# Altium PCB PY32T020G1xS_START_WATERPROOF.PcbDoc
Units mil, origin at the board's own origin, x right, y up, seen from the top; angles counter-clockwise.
Board outline 3313.26 x 4614.31 mil, 2 copper layers (Top Layer, Bottom Layer); 71 components, 60 nets, 191 pads, 58 vias.
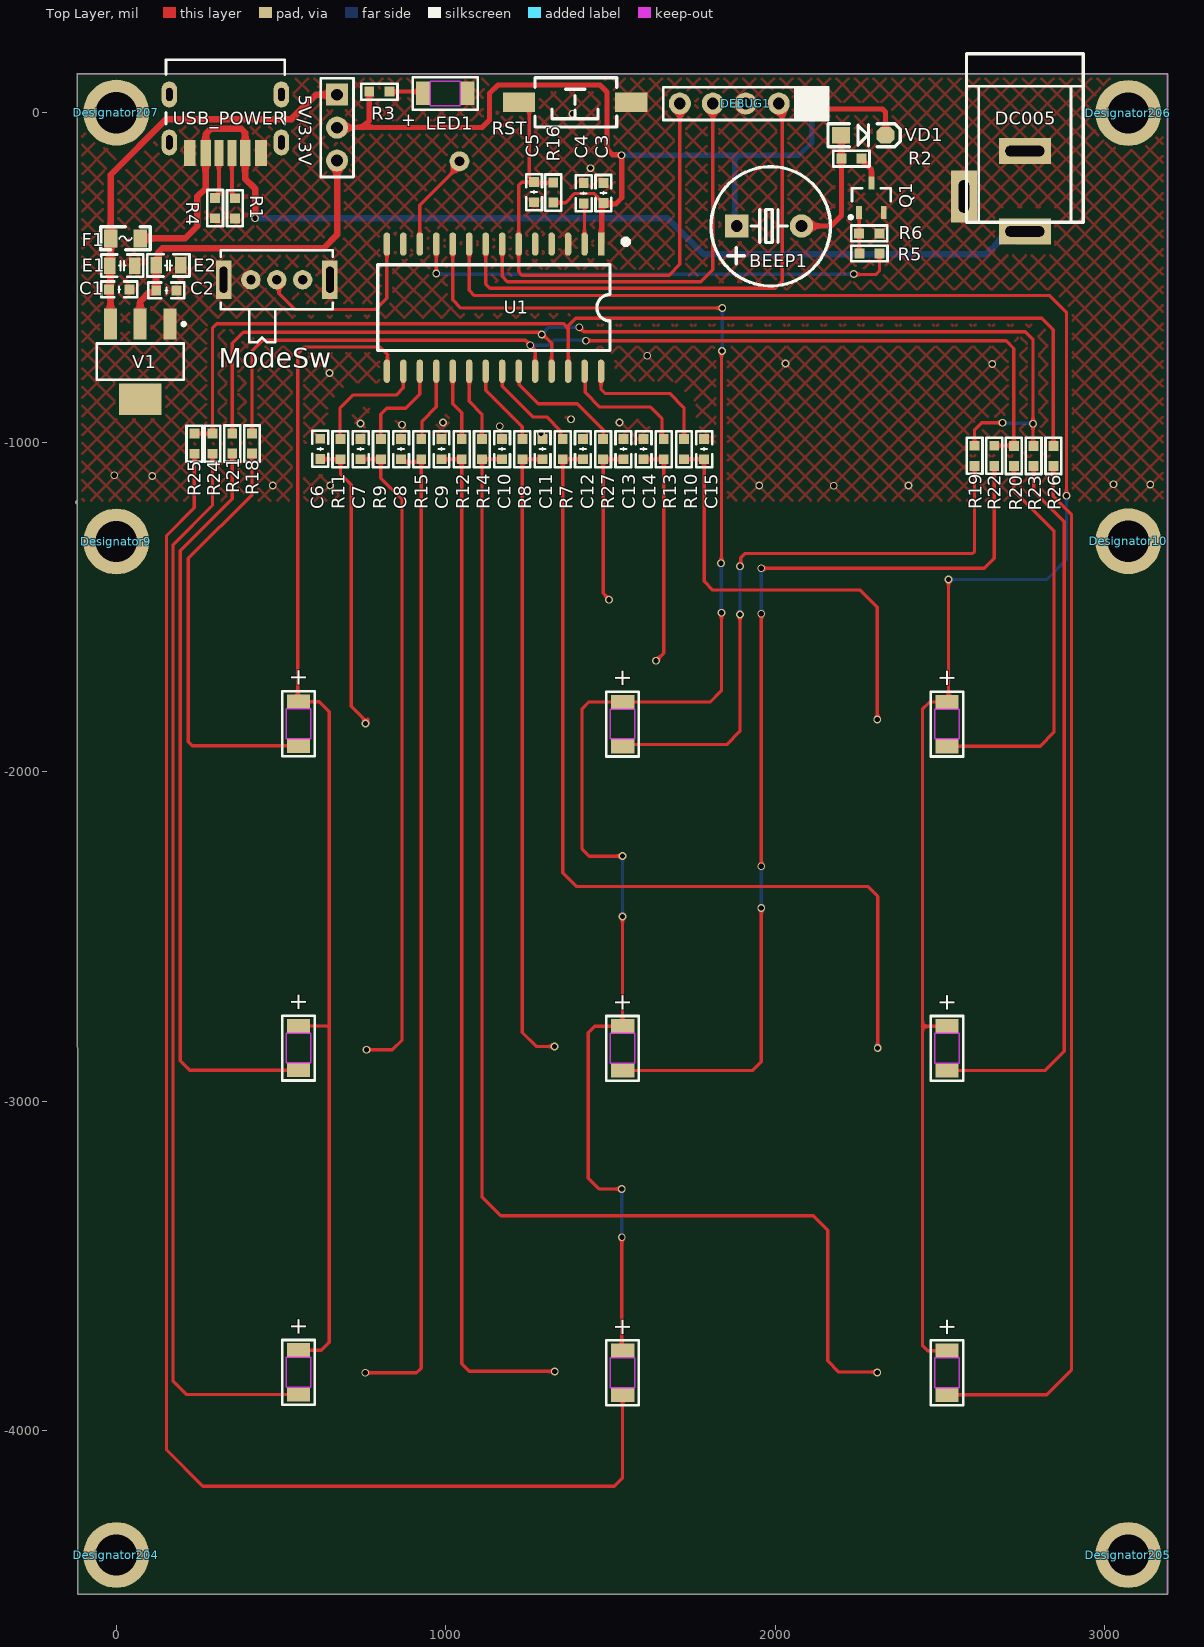
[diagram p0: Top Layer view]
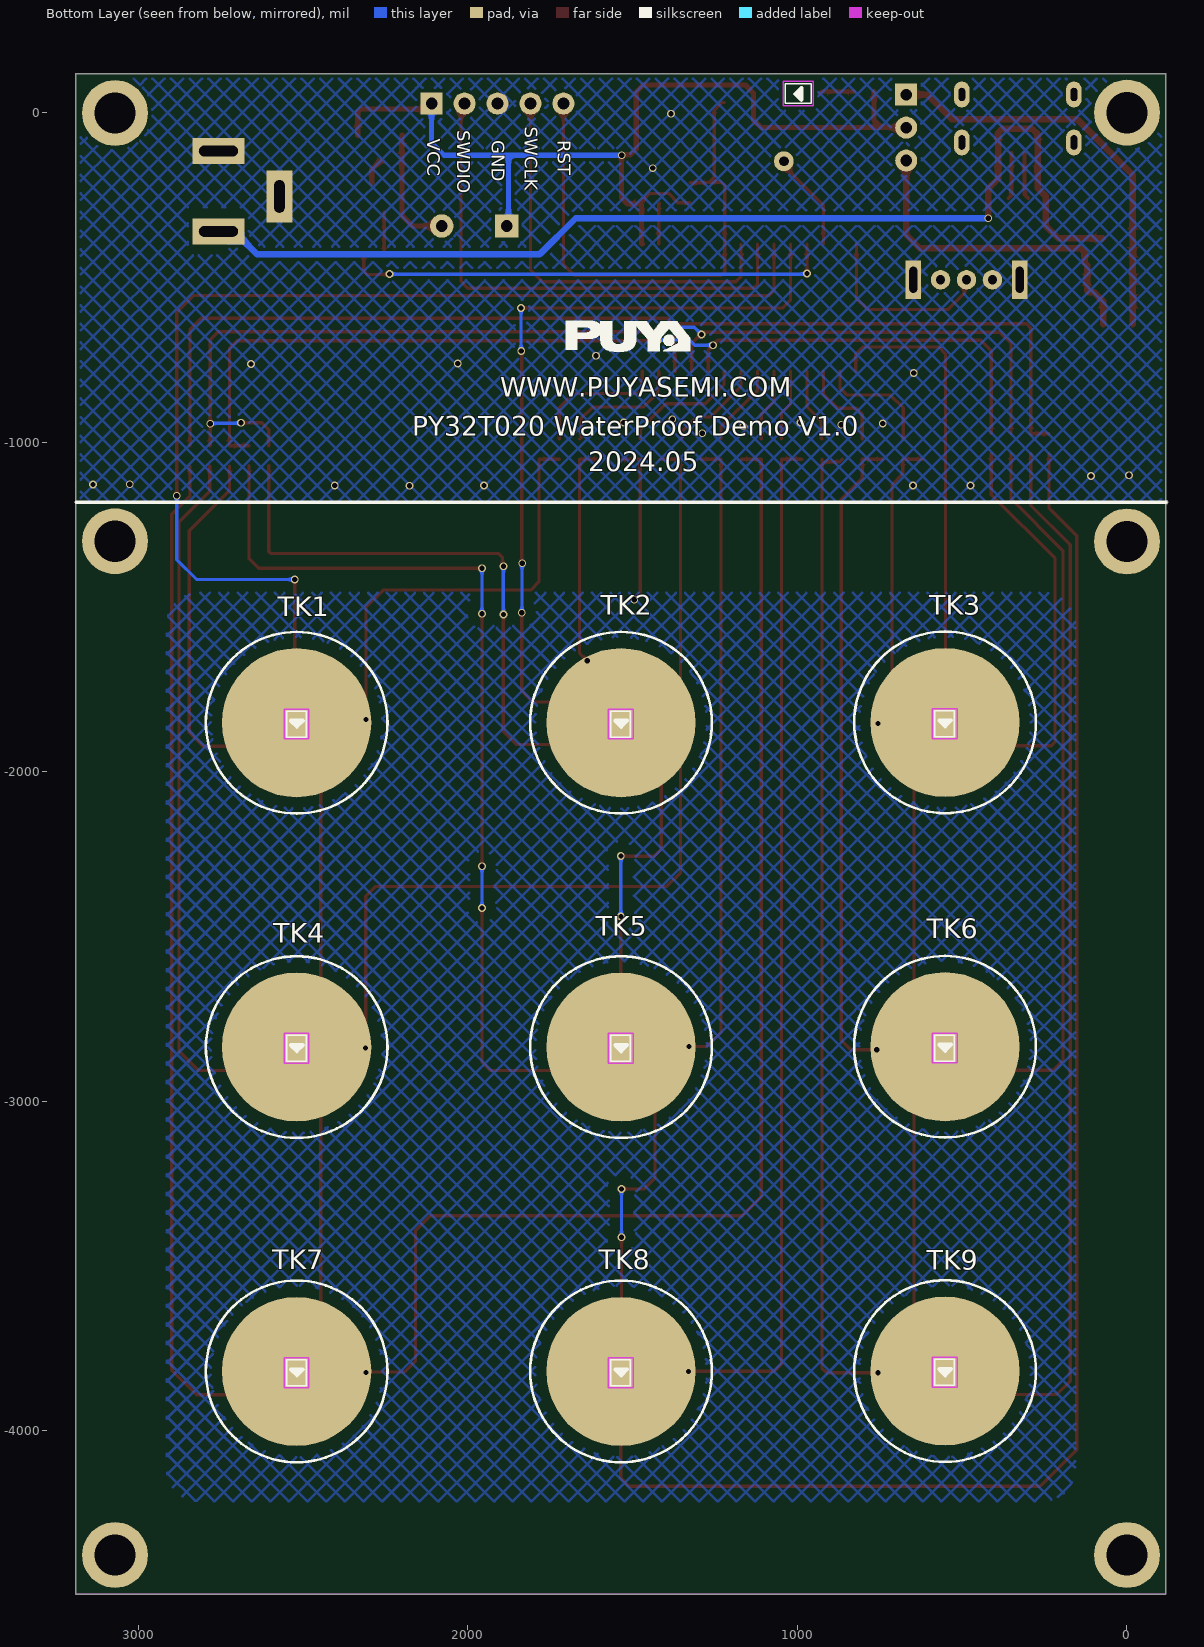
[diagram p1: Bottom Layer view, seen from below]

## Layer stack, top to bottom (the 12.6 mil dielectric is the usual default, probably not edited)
Top Solder: solder mask 0.4, Solder Resist, Dk 3.5
Top Layer: signal copper 1.4
Dielectric 1: dielectric 12.6, FR-4, Dk 4.8
Bottom Layer: signal copper 1.4
Bottom Solder: solder mask 0.4, Solder Resist, Dk 3.5

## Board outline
-117.65,-4495.93 3190.12,-4495.93 3189.95,-4494.9 3189.95,117.87 3189.43,118.38 -117.65,118.38 -118.17,117.87 -118.17,-1187.31 cw(c-118.12,-1182.29)

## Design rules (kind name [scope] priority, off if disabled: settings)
Clearance [InNet('TK1')] p1: gap=30.24 ignorepadtopadclearanceinfootprint=FALSE
Clearance Clearance_21 [InNet('TK2')] p2: gap=30.24 ignorepadtopadclearanceinfootprint=FALSE
Clearance Clearance_20 [InNet('TK3')] p3: gap=30.24 ignorepadtopadclearanceinfootprint=FALSE
Clearance Clearance_19 [InNet('TK4')] p4: gap=30.24 ignorepadtopadclearanceinfootprint=FALSE
Clearance Clearance_18 [InNet('TK5')] p5: gap=30.24 ignorepadtopadclearanceinfootprint=FALSE
Clearance Clearance_17 [InNet('TK6')] p6: gap=30.24 ignorepadtopadclearanceinfootprint=FALSE
Clearance Clearance_16 [InNet('TK7')] p7: gap=30.24 ignorepadtopadclearanceinfootprint=FALSE
Clearance Clearance_15 [InNet('TK8')] p8: gap=30.24 ignorepadtopadclearanceinfootprint=FALSE
Clearance Clearance_14 [InNet('TK9')] p9: gap=30.24 ignorepadtopadclearanceinfootprint=FALSE
Clearance Clearance_13 [InNet('TK_GNG')] p10: gap=30.24 ignorepadtopadclearanceinfootprint=FALSE
Clearance Clearance_12 [InNet('TK_GUARD')] p11: gap=30.24 ignorepadtopadclearanceinfootprint=FALSE
Clearance Clearance_25 [InNet('TK_GUARD_GNG')] p12: gap=30.24 ignorepadtopadclearanceinfootprint=FALSE
Clearance Clearance_23 [InNet('TK_SH_GND')] p13: gap=30.24 ignorepadtopadclearanceinfootprint=FALSE
Clearance Clearance_8 [InNet('NetR7_2')] p14: gap=30.24 ignorepadtopadclearanceinfootprint=FALSE
Clearance Clearance_22 [InNet('NetR8_2')] p15: gap=30.24 ignorepadtopadclearanceinfootprint=FALSE
Clearance Clearance_10 [InNet('TK_GUARD_GNG')] p16: gap=30.24 ignorepadtopadclearanceinfootprint=FALSE
Clearance Clearance_11 [InNet('TK_SH_GND')] p17: gap=30.24 ignorepadtopadclearanceinfootprint=FALSE
Clearance Clearance_7 [InNet('NetR9_2')] p18: gap=30.24 ignorepadtopadclearanceinfootprint=FALSE
Clearance Clearance_9 [InNet('NetR11_2')] p19: gap=30.24 ignorepadtopadclearanceinfootprint=FALSE
Clearance Clearance_6 [InNet('NetR10_2')] p20: gap=30.24 ignorepadtopadclearanceinfootprint=FALSE
Clearance Clearance_5 [InNet('NetR12_2')] p21: gap=30.24 ignorepadtopadclearanceinfootprint=FALSE
Clearance Clearance_4 [InNet('NetR13_2')] p22: gap=30.24 ignorepadtopadclearanceinfootprint=FALSE
Clearance Clearance_3 [InNet('NetR14_2')] p23: gap=30.24 ignorepadtopadclearanceinfootprint=FALSE
Clearance Clearance_2 [InNet('NetR15_2')] p24: gap=30.24 ignorepadtopadclearanceinfootprint=FALSE
Clearance Clearance_1 [All] p25: gap=10 ignorepadtopadclearanceinfootprint=FALSE except(0: Arc-Hole Track-Hole SMDPad-Hole THPad-Hole Via-Hole Fill-Hole Poly-Hole Region-Hole Text-Hole)
PlaneConnect PlaneConnect_1 [InNet('GND')] p1: planeconnectstyle=Direct reliefexpansion=20 reliefentries=4 reliefconductorwidth=10 reliefairgap=10
PlaneConnect [All] p2: planeconnectstyle=Direct reliefexpansion=20 reliefentries=4 reliefconductorwidth=10 reliefairgap=10
PolygonConnect PolygonConnect_1 [InNet('GND')] p1: connectstyle=Direct reliefconductorwidth=10 reliefentries=4 polygonreliefangle="90 Angle" airgapwidth=10
PolygonConnect [All] p2: connectstyle=Direct reliefconductorwidth=10 reliefentries=4 polygonreliefangle="90 Angle" airgapwidth=10
RoutingVias [All] p1: holewidth=28 width=50 viastyle="Through Hole" minholewidth=28 minwidth=50 maxholewidth=28 maxwidth=50
SolderMaskExpansion [All] p1: expansion=4 istentingtop=FALSE
Width [All] p1: maxlimit=23.62 minlimit=10 preferedwidth=10
29 further rules are at their usual default settings.

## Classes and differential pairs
component class PY32T020_StartKit_V1.0: BEEP1 C1 C2 C3 C4 C5 DEBUG1 E1 E2 F1 Q1 R1 R2 R3 R4 R5 R6 R7 R8 R9 R10 R11 R12 R13 R14 R15 R16 R18 R19 R20 R21 R22 R23 R24 R25 R26 RST U1 USB_POWER V1 VD1

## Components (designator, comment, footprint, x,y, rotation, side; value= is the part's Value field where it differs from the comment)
5V/3.3V "Comment" HDR2.54-LI-3P 669.96,-45.29 r270 top
BEEP1 "DC5V" "BEEP 5x9x5.5" 1980.89,-343.89 r270 top
C1 "104" "C 0603_L" 8.96,-536.29 r180 top
C2 "104" "C 0603_L" 151.96,-539.29 r180 top (schematic designator C3)
C3 "104" "C 0603_L" 1478.07,-243.93 r270 top
C4 "22NF" "C 0603_L" 1418.36,-244.52 r270 top
C5 "104" "C 0603_L" 1267.96,-241.29 r90 top
C6 "5PF" "C 0603_L" 619,-1020 r270 top (schematic designator C3)
C7 "5PF" "C 0603_L" 741.63,-1021 r90 top (schematic designator C3)
C8 "5PF" "C 0603_L" 864.26,-1021 r90 top (schematic designator C3)
C9 "5PF" "C 0603_L" 986.89,-1021 r90 top (schematic designator C3)
C10 "5PF" "C 0603_L" 1170.84,-1021 r90 top (schematic designator C3)
C11 "5PF" "C 0603_L" 1293.47,-1021 r90 top (schematic designator C3)
C12 "5PF" "C 0603_L" 1416.1,-1021 r90 top (schematic designator C3)
C13 "5PF" "C 0603_L" 1538.74,-1021 r90 top (schematic designator C3)
C14 "5PF" "C 0603_L" 1600.05,-1021 r90 top (schematic designator C3)
C15 "5PF" "C 0603_L" 1784,-1021 r90 top (schematic designator C3)
DC005 "Comment" DC-005 2756.96,-116.29 r90 top
DEBUG1 "ISP" ISP_DIP_2.54_5P 2110.15,27.72 r180 top
Designator9 "Comment" "M3 125X200"#1 0,-1300.4 r0 top
Designator10 "Comment" "M3 125X200"#2 3070.78,-1260.84 r0 top
Designator204 "Comment" "M3 125X200"#3 917.62,-3625.4 r0 top
Designator205 "Comment" "M3 125X200"#4 1567.95,-3583.28 r0 top
Designator206 "Comment" "M3 125X200"#5 2115.25,-689.08 r0 top
Designator207 "Comment" "M3 125X200"#6 166.83,-122.51 r0 top
E1 "10uF/10V" "C 0805_L" 17.96,-464.29 r0 top
E2 "10uF/10V" "C 0805_L" 158.37,-463.29 r0 top
F1 "500ma" "FU 0805" 27.96,-381.29 r180 top
LED1 "Comment" T-LED#1 993.96,57.71 r180 bottom
ModeSw "Comment" SK-12D07VG3 487,-507 r0 top
Q1 "SS8050" SOT23-3L 2291.65,-257.37 r0 top
R1 "5.1K" "R 0603_L" 360.03,-290.19 r90 top
R2 "200R" "R 0603_L" 2230.96,-139.29 r180 top
R3 "1K" "R 0603_L" 798.37,63.71 r180 top
R4 "5.1K" "R 0603_L" 300.03,-289.6 r90 top
R5 "1K" "R 0603_L" 2285.37,-427.29 r0 top
R6 "10K" "R 0603_L" 2284.81,-366.29 r180 top
R7 "4.3K" "R 0603_L" 1354.79,-1021 r270 top
R8 "4.3K" "R 0603_L" 1232.16,-1021 r270 top
R9 "4.3K" "R 0603_L" 802.95,-1021 r270 top
R10 "4.3K" "R 0603_L" 1722.68,-1021 r270 top
R11 "4.3K" "R 0603_L" 680.32,-1021 r270 top
R12 "4.3K" "R 0603_L" 1048.21,-1021 r270 top
R13 "4.3K" "R 0603_L" 1661.37,-1021 r270 top
R14 "4.3K" "R 0603_L" 1109.53,-1021 r270 top
R15 "4.3K" "R 0603_L" 925.58,-1021 r270 top
R16 "10K" "R 0603_L" 1325.96,-242.29 r270 top
R18 "1K" "R 0603_L" 411.89,-1003.95 r270 top
R19 "1K" "R 0603_L" 2604.32,-1041.12 r270 top
R20 "1K" "R 0603_L" 2723.59,-1041.66 r270 top
R21 "1K" "R 0603_L" 351.89,-1003.95 r270 top
R22 "1K" "R 0603_L" 2664.32,-1041.12 r270 top
R23 "1K" "R 0603_L" 2783.59,-1041.66 r270 top
R24 "1K" "R 0603_L" 291.89,-1004.54 r270 top
R25 "1K" "R 0603_L" 236.89,-1004.54 r270 top
R26 "1K" "R 0603_L" 2843.59,-1041.66 r270 top
R27 "4.3K" "R 0603_L" 1477.42,-1021 r270 top
RST "6x6x5" "TSW SMD-3*6*5" 1392.05,31.19 r180 top
TK1 "Comment" T-LED#2 2519.62,-1851.19 r90 bottom
TK2 "Comment" T-LED#2 1535.36,-1851.19 r90 bottom
TK3 "Comment" T-LED#2 552.18,-1850.08 r90 bottom
TK4 "Comment" T-LED#2 2519.62,-2835.44 r90 bottom
TK5 "Comment" T-LED#2 1535.36,-2835.44 r90 bottom
TK6 "Comment" T-LED#2 552.18,-2834.34 r90 bottom
TK7 "Comment" T-LED#2 2519.62,-3819.69 r90 bottom
TK8 "Comment" T-LED#2 1535.36,-3819.69 r90 bottom
TK9 "Comment" T-LED#2 552.18,-3818.59 r90 bottom
U1 "PY32T020G16" SOP28_L 1146.02,-591.58 r270 top
USB_POWER "USB-C" USB-C/S_C 331.05,155.67 r180 top (schematic designator USB_POWER1)
V1 "AMS1117-3V3" SOT223_N 72.51,-755.46 r270 top
VD1 "A7" SOD-123 2266.96,-68.29 r0 top

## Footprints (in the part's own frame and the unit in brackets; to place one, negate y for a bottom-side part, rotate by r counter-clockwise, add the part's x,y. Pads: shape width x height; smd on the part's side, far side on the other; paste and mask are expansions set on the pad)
"BEEP 5x9x5.5" [mm] "5*9*5.5mm(脚距,直径,高度)"
  rect 1.8x1.8 hole 0.9: 1(0,-2.5)
  round 1.8 hole 0.9: 2(0,2.5)
  silkscreen extent -4.57,-4.47 4.62,4.73, body extent -4.5,-4.5 4.5,4.5, height 5.45
"C 0603_L" [mil] "无极性贴片电容"
  rect 30x30 smd: 1(-30.59,0) 2(30.59,0)
  silkscreen extent -55,-24 55,24, body extent -31,-16 31,16, height 32
"C 0805_L" [mil] "无极性贴片电容"
  rect 35x50 smd: 1(-37.4,0) 2(37.4,0)
  silkscreen extent -64,-34 64,34, body extent -39,-24 39,24, height 20
DC-005 [mm] "5.5*2.1mm，DC30V,2.5A"
  rect 2x4 hole 0.8 slot 3 at 90 deg: 1(-6.2,0) 2(0,0)
  rect 4x2 hole 0.8 slot 2.5 at 0 deg: 3(-3.5,4.7)
  silkscreen extent -5.48,-4.5 7.5,4.5, body extent -6.55,-4.5 7.5,4.8, height 11.2
"FU 0805" [mil] "贴片保险丝"
  rect 40x55 smd: 1(-45,0) 2(45,0)
  silkscreen extent -75,-35 75,35, body extent -39,-24 39,24, height 20
HDR2.54-LI-3P [mm] "排针，3脚"
  rect 1.7x1.7 hole 0.9: 1(-2.54,0)
  round 1.7 hole 0.9: 2(0,0) 3(2.54,0)
  silkscreen extent -3.81,-1.27 3.81,1.27, body extent -3.81,-1.27 3.81,1.27, height 8.5
ISP_DIP_2.54_5P [mm] "5P 下载端口"
  rect 1.7x1.7 hole 0.9: 1(0,0)
  round 1.7 hole 0.9: 2(2.54,0) 3(5.08,0) 4(7.62,0) 5(10.16,0)
  silkscreen extent -1.27,-1.27 11.43,1.27
"M3 125X200"#1 [mil] "M3螺丝孔，孔125Mil，焊盘200Mil"
  round 200 hole 125: 1(0,-1)
"M3 125X200"#2 [mil] "M3螺丝孔，孔125Mil，焊盘200Mil"
  round 200 hole 125: 1(0.07,-39.56)
"M3 125X200"#3 [mil] "M3螺丝孔，孔125Mil，焊盘200Mil"
  round 200 hole 125: 1(-917.62,-751.38)
"M3 125X200"#4 [mil] "M3螺丝孔，孔125Mil，焊盘200Mil"
  round 200 hole 125: 1(1502.83,-793.5)
"M3 125X200"#5 [mil] "M3螺丝孔，孔125Mil，焊盘200Mil"
  round 200 hole 125: 1(955.53,688.08)
"M3 125X200"#6 [mil] "M3螺丝孔，孔125Mil，焊盘200Mil"
  round 200 hole 125: 1(-166.83,122.51)
"R 0603_L" [mil] "1/10W贴片电阻"
  rect 30x30 smd: 1(-30.59,0) 2(30.59,0)
  silkscreen extent -55,-24 55,24, body extent -31,-16 32,16, height 16
SK-12D07VG3 [mm] "侧脚支架小型拨动开关"
  rect 1.2x3 hole 0.6 slot 2 at 90 deg unplated: 0(-4.1,0) 0(4.1,0)
  round 1.5 hole 0.7 unplated: 1(-2,0) 2(0,0) 3(2,0)
  silkscreen extent -4.32,-4.83 4.32,2.29, body extent -4.3,-4.85 4.3,2.25, height 4.75
SOD-123 [mil] "2.7x1.6X1.1mm（长宽高，不包括引脚）"
  rect 55x50 smd: 1(-67.5,0)
  oct 55x50 smd: 2(67.5,0)
  silkscreen extent -108,-35 112,35, body extent -73,-31 73,31, height 48
SOP28_L [mm] "17.9*10.6*2.6mm（长宽高）"
  rect 1.8x0.5 smd: 1(-4.9,8.255)
  oval 1.8x0.5 smd: 2(-4.9,6.985) 3(-4.9,5.715) 4(-4.9,4.445) 5(-4.9,3.175) 6(-4.9,1.905) 7(-4.9,0.635) 8(-4.9,-0.635) 9(-4.9,-1.905) 10(-4.9,-3.175) 11(-4.9,-4.445) 12(-4.9,-5.715) 13(-4.9,-6.985) 14(-4.9,-8.255) 15(4.9,-8.255) 16(4.9,-6.985) 17(4.9,-5.715) 18(4.9,-4.445) 19(4.9,-3.175) 20(4.9,-1.905) 21(4.9,-0.635) 22(4.9,0.635) 23(4.9,1.905) 24(4.9,3.175) 25(4.9,4.445) 26(4.9,5.715) 27(4.9,6.985) 28(4.9,8.255)
  silkscreen extent -5.23,-8.95 3.3,10.31, body extent -5.15,-8.95 5.15,8.95, height 2.7
SOT23-3L [mm] "3x1.3x1mm(长宽高)"
  rect 0.45x1 smd: 1(-0.95,-1.143) 2(0.95,-1.143) 3(0,1.125)
  silkscreen extent -1.72,-1.65 1.5,0.7, body extent -1.5,-1.2 1.5,1.2, height 1.05
SOT223_N [mm] "SOT223, 4-Leads, Body 6.5x3.5mm, Pitch 2.3mm, Lead Span 7mm, IPC Medium Density"
  rect 2.4x1 smd: 1(-2.9,2.3) 2(-2.9,0) 3(-2.9,-2.3)
  rect 2.4x3.3 smd: 4(2.9,0)
  silkscreen extent -3.02,-3.35 1.4,3.48, body extent -1.85,-3.35 1.85,3.35, height 1.7
T-LED#1 [mm]
  rect 1.1x1.8 smd far side: 1(1.598,0.025) 2(-1.802,0.025)
  Keep-Out Layer lines w0.1: 1.048,-0.925 1.048,0.975 -1.252,0.975 -1.252,-0.925 1.048,-0.925
  silkscreen extent -1.1,-0.73 0.9,0.77
T-LED#2 [mm]
  rect 1.1x1.8 smd far side: 1(1.598,0.025) 2(-1.802,0.025)
  round 11.5 smd paste-15 mask+0.5: Touch(0,0)
  Keep-Out Layer lines w0.1: -1.252,-0.925 -1.252,0.975 1.048,0.975 1.048,-0.925 -1.252,-0.925
  silkscreen extent -7,-7 7,7
"TSW SMD-3*6*5" [mm] "3*6*5mm"
  rect 2.5x1.5 smd: 1(-4.318,0) 2(4.318,0)
  silkscreen extent -3.21,-1.9 3.09,1.9, body extent -4.6,-1.75 4.6,1.75, height 5.1
USB-C/S_C [mm] "Type-C 6P母座"
  oval 1.2x2 hole 0.5 slot 1.1 at 90 deg: 0(-4.32,6.25) 0(4.32,6.25)
  oval 1.2x2 hole 0.5 slot 1 at 90 deg: 0(-4.32,2.55) 0(4.32,2.55)
  rect 0.7x2 smd: A5(-0.5,7.05) B5(0.5,7.05)
  rect 0.8x2 smd: A9(1.52,7.05) B9(-1.52,7.05)
  rect 0.9x2 smd: A12(2.75,7.05) B12(-2.75,7.05)
  silkscreen extent -4.57,-0.13 4.57,4.83, body extent -4.47,0 4.48,7.05, height 3.16

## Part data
BEEP1: library part BEEP, "蜂鸣器"
C1 C2 C3 C4 C5 C6 C7 C8 C9 C10 C11 C12 C13 C14 C15: library part C, "无极性贴片电容"
DEBUG1: library part ISP_5Pin, "程序下载端口"
E1 E2: library part C-CM, "贴片电解电容"
F1: library part FU, "贴片保险丝"
Q1: library part 8050-DIP, "高频放大-NPN型"
R1 R4: library part R
R2 R3 R5 R6 R7 R8 R9 R10 R11 R12 R13 R14 R15 R16 R18 R19 R20 R21 R22 R23 R24 R25 R26 R27: library part R, "贴片电阻"
RST: library part "TSW DIP-2Pin-6x6", "2脚直插6x6轻触开关"
USB_POWER: library part USB-C_6P/S, "USB-C_6P型母接口"
V1: library part AMS1117, "三端稳压芯片"
VD1: library part DIODE

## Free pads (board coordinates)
  round 60 hole 30: 2(1041.36,-147.52)

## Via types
v1: diameter 23.62, hole 15.75, Top Layer to Bottom Layer, 58 vias

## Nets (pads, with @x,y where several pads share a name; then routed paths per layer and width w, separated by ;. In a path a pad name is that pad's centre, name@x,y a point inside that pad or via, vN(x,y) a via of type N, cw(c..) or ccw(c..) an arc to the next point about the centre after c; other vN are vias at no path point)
3.3V: 5V/3.3V.3 C2.2 E2.1 V1.2 | length 1039.4
  Top Layer w19.68: V1.2 72.51,-572.74 100.81,-544.45 116.21,-544.45 C2.2 121.17,-539.09 121.17,-463.5 E2.1 128.62,-455.63 128.62,-422.51 140.15,-410.98 629.28,-410.98 669.96,-370.29 5V/3.3V.3
BEEP: R5.2 U1.11 | length 1497
  Top Layer w10: v1(970.89,-487.89) 971.02,-487.76 U1.11 ; v1@2237.89,-486.2 v1(2237.89,-489.89) 2239.29,-491.29 2304.96,-491.29 2315.96,-480.29 R5.2
  Bottom Layer w10: v1(970.89,-487.89) 972.89,-489.89 v1(2237.89,-489.89)
CMOD: C4.2 U1.2 | length 124.7
  Top Layer w10: C4.2 1421.02,-277.77 U1.2
COM0: R24.1 R25.1 R26.1 U1.26 | length 3452.6
  Top Layer w10: R25.1 R24.1 291.89,-653.89 304.89,-640.89 1357.89,-640.89 1371.89,-654.89 ; U1.26 1371.89,-783.63 1371.89,-654.89 ; R26.1 2843.59,-658.78 2808.89,-624.08 1393.78,-624.08 1371.89,-645.97 1371.89,-654.89
COM1: R19.1 R21.1 R23.1 U1.25 | length 3429.8
  Top Layer w10: R21.1 351.89,-699.89 385.89,-665.89 1286.89,-665.89 1321.02,-700.02 U1.25 ; v1(1404.89,-650.89) 1418.89,-664.89 2757.89,-664.89 2781.89,-688.89 v1(2781.89,-943.89) 2781.89,-1009.37 R23.1 ; R19.1 2604.32,-962.46 2625.89,-940.89 v1(2688.89,-940.89)
  Bottom Layer w10: v1(1290.89,-672.89) 1312.89,-650.89 v1(1404.89,-650.89) ; v1(2688.89,-940.89) 2690.39,-942.39 2780.39,-942.39 v1(2781.89,-943.89)
COM2: R18.1 R20.1 R22.1 U1.24 | length 3038.6
  Top Layer w10: R18.1 411.89,-722.89 443.89,-690.89 1241.89,-690.89 v1(1256.46,-705.46) 1271.02,-720.02 U1.24 ; v1(1424.89,-691.89) 2699.89,-691.89 2723.59,-715.59 R20.1 2723.05,-1010.53 R22.1
  Bottom Layer w10: v1(1256.46,-705.46) 1311.32,-705.46 1326.89,-689.89 1422.89,-689.89 v1(1424.89,-691.89)
GND: C1.1 C2.1 C3.1 C4.1 C5.1 C6.1 C7.2 C8.2 C9.2 C10.2 C11.2 C12.2 C13.2 C14.2 C15.2 DC005.2 DC005.3 DEBUG1.3 E1.2 E2.2 LED1.2 ModeSw.0 ModeSw.1 Q1.2 R1.1 R4.1 R6.1 RST.1 U1.3 USB_POWER.A12 USB_POWER.B12 V1.1
  other v1: 2176.96,-1132.29 474.96,-1131.29 648.96,-1131.29 1950.96,-1131.29 2403.96,-1131.29 3137.75,-1127.95 3025.96,-1127.29 108.96,-1102.29 -6.04,-1100.29 1289.12,-972.76 1163.73,-951.27 867,-947 741,-943 991,-940 1527,-940.3 1379.59,-930.16 646.96,-790.29 2657.96,-762.29 2030.96,-761.29 1610.96,-737.45 1438.96,-168.29 1383.96,-3.29
NetBEEP1_2: BEEP1.2 R2.2 VD1.1 | length 378.3
  Top Layer w15.75: BEEP1.2 2168.36,-343.89 2200.37,-311.88 R2.2 2200.37,-69.2 VD1.1
NetC5_2: 
NetC6_2: 
NetC7_1: 
NetLED1_1: LED1.1 R3.1 | length 106.1
  Top Layer w10: R3.1 R3.1@830.35,62.32
  Top Layer w11.81: R3.1 926.03,63.71 LED1.1
NetLED2_2: R18.2 TK3.2 | length 1294.7
  Top Layer w10: R18.2 411.89,-1159 218.36,-1352.52 218.36,-1909.52 229.88,-1921.03 TK3.2
NetLED3_2: R19.2 TK2.2 | length 1879.7
  Top Layer w10: TK2.2 1541.02,-1917.45 1852.43,-1917.45 1892.36,-1877.52 v1(1892.36,-1522.52) ; v1(1892.36,-1376.52) 1894.97,-1373.91 1894.97,-1350.58 1908.03,-1337.52 2598.46,-1337.52 2604.32,-1331.66 R19.2
  Bottom Layer w10: v1(1892.36,-1522.52) v1(1892.36,-1376.52)
NetLED4_2: R20.2 TK1.2 | length 1200.7
  Top Layer w10: TK1.2 2803.75,-1922.14 2845.36,-1880.52 2845.36,-1268.52 2723.59,-1146.75 R20.2
NetLED5_2: R21.2 TK6.2 | length 2277.9
  Top Layer w10: R21.2 351.89,-1172 194.36,-1329.52 194.36,-2876.52 223.13,-2905.28 TK6.2
NetLED6_2: R22.2 TK5.2 | length 2930
  Top Layer w10: TK5.2 1931.5,-2906.39 1957.36,-2880.52 v1(1957.36,-2413.52) ; v1(1957.36,-2286.52) v1(1957.36,-1520.52) ; v1(1957.36,-1382.52) 2634.36,-1382.52 2664.32,-1352.56 R22.2
  Bottom Layer w10: v1(1957.36,-2413.52) v1(1957.36,-2286.52) ; v1(1957.36,-1520.52) v1(1957.36,-1382.52)
NetLED7_2: R23.2 TK4.2 | length 2194.4
  Top Layer w10: TK4.2 2818.5,-2906.39 2876.36,-2848.52 2876.36,-1241.52 2783.59,-1148.75 R23.2
NetLED8_2: R24.2 TK9.2 | length 3261.3
  Top Layer w10: R24.2 291.89,-1192 172.36,-1311.52 172.36,-3849.52 212.38,-3889.54 TK9.2
NetLED9_2: R25.2 TK8.2 | length 4749.6
  Top Layer w10: R25.2 236.89,-1199 152.36,-1283.52 152.36,-4057.36 262.89,-4167.89 1511.36,-4167.89 1536.34,-4142.92 TK8.2
NetLED10_2: R26.2 TK7.2 | length 3174.8
  Top Layer w10: TK7.2 2823.24,-3890.64 2898.36,-3815.52 2898.36,-1218.52 2843.59,-1163.75 R26.2
NetQ1_1: Q1.1 R5.1 R6.2 | length 125.5
  Top Layer w10: R5.1@2252.97,-427.29 2254.25,-426.01 Q1.1
NetQ1_3: Q1.3 R2.1 | length 77.4
  Top Layer w15.75: R2.1@2265.97,-146.36 2291.65,-172.04 Q1.3
NetR1_2: R1.2 USB_POWER.A5 | length 141.6
  Top Layer w11.81: USB_POWER.A5 350.73,-250.31 R1.2
NetR4_2: R4.2 USB_POWER.B5 | length 141.8
  Top Layer w11.81: R4.2 311.36,-247.68 USB_POWER.B5
NetR7_2: C12.1 R7.2 TK4.Touch | length 2761.9
  Top Layer w10: C12.1 R7.2 1354.79,-2306.79 1396,-2348 2280,-2348 2310.36,-2378.36 v1(2310.36,-2838.52)
NetR8_2: C11.1 R8.2 TK5.Touch | length 1915.6
  Top Layer w10: C11.1 R8.2 1232.16,-2791.16 1274.52,-2833.52 v1(1329.36,-2833.52)
NetR9_2: C7.1 R9.2 TK6.Touch | length 1970.4
  Top Layer w10: C7.1 R9.2 802.95,-1108.74 867,-1172.79 867,-2814.52 838,-2843.52 v1(759.36,-2843.52)
NetR10_2: C15.1 R10.2 TK1.Touch | length 1330.9
  Top Layer w10: R10.2 C15.1 1784,-1422.52 1810,-1448.52 2257.36,-1448.52 2309.36,-1500.52 v1(2309.36,-1841.52)
NetR11_2: C6.2 R11.2 TK3.Touch | length 912.9
  Top Layer w10: C6.2 620,-1051.59 R11.2 680.32,-1096.11 712.92,-1128.71 712.92,-1801.07 762.71,-1850.86 762.71,-1839.76 ; v1(755.9,-1853.52) v1@760.63,-1848.79
NetR12_2: C9.1 R12.2 TK8.Touch | length 3098
  Top Layer w10: C9.1 R12.2 1048.21,-3796.73 1071,-3819.52 v1(1330.36,-3819.52)
NetR13_2: C14.1 R13.2 TK2.Touch | length 682.4
  Top Layer w10: C14.1 R13.2 1661.37,-1639.63 v1(1638,-1663)
NetR14_2: C10.1 R14.2 TK7.Touch | length 3952.2
  Top Layer w10: C10.1 R14.2 1109.53,-3289.18 1167.24,-3346.89 2114.89,-3346.89 2158.89,-3390.89 2158.89,-3787.89 2192.52,-3821.52 2308.36,-3821.52 v1(2309.36,-3822.52)
NetR15_2: C8.1 R15.2 TK9.Touch | length 2999
  Top Layer w10: v1(755.36,-3823.52) 755.74,-3823.89 911,-3823.89 925.58,-3809.31 R15.2@925.58,-1060.17 ; C8.1 872.84,-1060.17 R15.2@925.58,-1060.17 ; R15.2 R15.2@925.58,-1060.17
NRST: C5.2 DEBUG1.5 R16.1 RST.2 U1.6 | length 1624.2
  Top Layer w10: RST.2 1228.36,31.19 1252.89,6.66 1252.89,-195.63 C5.2 1230.55,-210.7 1221.02,-220.23 U1.6 1221.02,-483.02 1230.89,-492.89 1677.89,-492.89 1710.15,-460.63 DEBUG1.5 ; C5.2@1274.96,-212.7 R16.1@1325.96,-212.7
OSCIN: U1.4
OSCOUT: U1.5
SEG0: TK3.1 TK6.1 TK9.1 U1.15 | length 3616.2
  Top Layer w10: TK9.1 621.51,-3755.68 646.36,-3730.82 646.36,-2774.17 ; TK6.1 643.62,-2771.43 646.36,-2774.17 ; U1.15 822.88,-782.64 822.88,-735.9 823.89,-734.89 799.89,-710.89 570.89,-710.89 550.89,-730.89 550.89,-1784.91 TK3.1 616.02,-1787.17 646.36,-1817.52 646.36,-2774.17
SEG1: TK2.1 TK5.1 TK8.1 U1.10 | length 4847.9
  Top Layer w10: U1.10 1021.02,-568.02 1045.89,-592.89 v1(1838.89,-592.89) ; v1@1535.89,-3263.89 v1(1533.89,-3265.89) 1464.74,-3265.89 1432.36,-3233.52 1432.36,-2791.52 1451.35,-2772.53 TK5.1 1535.89,-2772.08 v1(1535.89,-2438.89) ; v1(1535.89,-2255.89) 1434.74,-2255.89 1413.36,-2234.52 1413.36,-1808.52 1433.61,-1788.28 TK2.1 1802.5,-1788.28 1836.36,-1754.41 v1(1836.36,-1517.52) ; TK8.1 1534.13,-3754.57 v1(1534.13,-3412.65) v1@1536.89,-3409.89 ; v1(1835.36,-1367.52) 1836.63,-1366.26 1836.63,-724.15 v1(1837.89,-722.89)
  Bottom Layer w10: v1(1533.89,-3265.89) 1533.89,-3412.41 v1(1534.13,-3412.65) ; v1(1535.89,-2438.89) v1(1535.89,-2255.89) ; v1(1835.36,-1367.52) 1835.86,-1368.02 1835.86,-1517.02 v1(1836.36,-1517.52) ; v1(1837.89,-722.89) 1838.89,-721.89 v1(1838.89,-592.89)
SEG2: TK1.1 TK4.1 TK7.1 U1.9 | length 5656.7
  Top Layer w10: U1.9 1071.02,-539.02 1086.89,-554.89 2832.89,-554.89 2883.36,-605.36 v1(2883.36,-1162.52) ; TK7.1 2462.36,-3756.78 2446.36,-3740.78 2446.36,-2772.53 ; TK4.1 2446.36,-2772.53 ; v1(2525.36,-1416.52) 2525.36,-1783.5 TK1.1 2468.61,-1788.28 2446.36,-1810.52 2446.36,-2772.53
  Bottom Layer w10: v1(2525.36,-1416.52) 2823.36,-1416.52 2883.36,-1356.52 v1(2883.36,-1162.52)
SWCLK: DEBUG1.4 U1.7 | length 1263.4
  Top Layer w10: U1.7 1171.02,-497.02 1186.89,-512.89 1773.89,-512.89 1810.15,-476.63 DEBUG1.4
SWDIO: DEBUG1.2 U1.8 | length 1579.3
  Top Layer w10: U1.8 1121.02,-520.02 1133.89,-532.89 1999.89,-532.89 2020.89,-511.89 2020.89,16.98 DEBUG1.2
TK1: R7.1 U1.22 | length 307
  Top Layer w10: U1.22 1171.02,-830.74 1263.64,-923.35 1306.25,-923.35 1349.16,-966.27 1349.16,-984.78 R7.1
TK2: R13.1 U1.27 | length 396.7
  Top Layer w10: U1.27 1421.02,-800.31 1421.49,-800.31 1422.88,-800.33 1422.88,-848.78 1467.35,-893.25 1621.25,-893.25 1655.74,-927.74 1655.74,-984.78 R13.1
TK3: R10.1 U1.28 | length 425.6
  Top Layer w10: U1.28 1471.02,-840.02 1483,-852 1680,-852 1722.68,-894.68 R10.1
TK4: R11.1 U1.16 | length 362.7
  Top Layer w10: R11.1 679,-989.09 679,-896 718.24,-856.76 849.19,-856.76 871.02,-834.93 U1.16
TK5: R9.1 U1.17 | length 288.2
  Top Layer w10: R9.1 802.95,-915.05 821,-897 878,-897 921.02,-853.98 U1.17
TK6: R15.1 U1.18 | length 224.7
  Top Layer w10: R15.1 928,-987.99 928,-936 971.02,-892.98 U1.18
TK7: R12.1 U1.19 | length 217.2
  Top Layer w10: U1.19 1021.02,-882.96 1048.21,-910.15 R12.1
TK8: R14.1 U1.20 | length 221.9
  Top Layer w10: U1.20 1071.02,-876.06 1109.53,-914.56 R14.1
TK9: R8.1 U1.21 | length 251.9
  Top Layer w10: U1.21 1121.02,-842.02 1232.16,-953.16 R8.1
TK_GNG: 
TK_GUARD: R27.1 U1.23 | length 381.7
  Top Layer w10: U1.23 1222.88,-786.35 1222.88,-825.69 1252.59,-855.41 1280.3,-883.11 1399.08,-883.11 1414.56,-898.59 1477.42,-961.46 R27.1
TK_GUARD_GNG: C13.1 R27.2 | length 495
  Top Layer w10: v1(1495,-1478) 1495,-1475.24 1477.42,-1457.66 R27.2 C13.1
TK_SH: ModeSw.2 U1.14 | length 575.2
  Top Layer w10: ModeSw.2@493.37,-500.52 493.37,-548.36 542,-597 787,-597 821.02,-562.98 U1.14 U1.14@820.19,-397.84
TK_SH_GND: 
TXD: pad.2 U1.12 | length 301
  Top Layer w10: U1.12 921.02,-280.86 1041.36,-160.52 pad.2
V5V: 5V/3.3V.1 C1.2 E1.1 F1.2 V1.3 | length 1241.1
  Top Layer w19.68: V1.3 -17.54,-640.79 -17.54,-536.29 -17.54,-464.29 -17.54,-381.79 F1.2 -17.04,-188.29 151.96,-19.29 531.96,-19.29 605.96,54.71 5V/3.3V.1
VBUS: DC005.1 F1.1 USB_POWER.A9 USB_POWER.B9 | length 3291.9
  Top Layer w19.68: F1.1 208.96,-381.29 245.96,-344.29 245.96,-254.29 271.2,-229.05 USB_POWER.A9 271.54,-121.56 271.54,-64.72 287.28,-48.98 379.36,-48.98 390.89,-60.51 USB_POWER.B9 390.89,-200.22 420.96,-230.29 v1(420.96,-320.29)
  Bottom Layer w19.68: v1(420.96,-320.29) 1672.96,-320.29 1782.96,-430.29 2638.96,-430.29 2679.34,-389.91 2727.44,-389.91 DC005.1
VCC: 5V/3.3V.2 BEEP1.1 C3.2 DEBUG1.1 R3.2 R16.2 U1.1 VD1.2 | length 3001.9
  Top Layer w10: R16.2 1363.37,-272.88 1391.14,-245.11 1448.66,-245.11 C3.2
  Top Layer w15.75: 5V/3.3V.2 745.96,-45.29 ; R3.2 767.78,-23.47 745.96,-45.29 ; U1.1 1472.99,-396.7 1472.99,-279.6 C3.2 1480.43,-276.89 1515.36,-276.89 1533.89,-258.36 1533.89,-130.22 1531.46,-127.78 1506.78,-127.78 1488.96,-109.96 1488.96,62.71 1467.96,83.71 1157.96,83.71 1132.96,58.71 1132.96,-22.29 1109.96,-45.29 745.96,-45.29 ; DEBUG1.1 2126.88,10.99 2325.24,10.99 2334.46,1.77 VD1.2
  Bottom Layer w15.75: v1(1532.96,-129.29) 1876.96,-129.29 ; BEEP1.1 1876.96,-338.39 1876.96,-129.29 ; DEBUG1.1 2110.15,-91.1 2071.96,-129.29 1876.96,-129.29
pads on no net: Designator9.1 Designator10.1 Designator204.1 Designator205.1 Designator206.1 Designator207.1 ModeSw.3 U1.13 USB_POWER.0 V1.4

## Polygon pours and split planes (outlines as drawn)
GND on Bottom Layer "GND_L02_P043" (hatched 45Degree grid 40 track 8, remove dead copper, pour order 43): -113.04,119.71 -115.04,117.71 -115.04,-1181.29 3198.96,-1181.29 3195.96,-1178.29 3195.96,119.71
TK_GUARD_GNG on Bottom Layer "Bottom Layer-TK_GUARD_GNG" (hatched 45Degree grid 40 track 8, remove dead copper, pour order 34): 157.94,-1556.94 cw(c257.94,-1556.94) 257.94,-1456.94 2813.84,-1456.94 cw(c2813.84,-1556.94) 2913.84,-1556.94 2913.84,-4112.84 cw(c2813.84,-4112.84) 2813.84,-4212.84 257.94,-4212.84 cw(c257.94,-4112.84) 157.94,-4112.84
GND on Top Layer "GND_L01_P044" (hatched 45Degree grid 40 track 8, remove dead copper, pour order 44): -114,124 -114,-1177 3188,-1177 3188,120 3195,127

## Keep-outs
Keep-Out Layer:
  lines w1: 3189.43,-4495.41 3189.43,117.87 -117.65,117.87 -117.65,-4495.41 3190.12,-4495.41

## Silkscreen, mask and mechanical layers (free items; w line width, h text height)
Bottom Overlay:
  drawing of 448 lines, arcs and shapes, not listed
  text "SWCLK" at 1827.94,-43.42 h39.37 r90
  text "SWDIO" at 2032.94,-53.42 h39.37 r90
  text "VCC" at 2122.94,-78.42 h39.37 r90
  text "RST" at 1727.94,-83.42 h39.37 r90
  text "GND" at 1927.62,-84.33 h39.37 r90
  text "WWW.PUYASEMI.COM" at 1902.36,-862.52 h59.06
  text "PY32T020 WaterProof Demo V1.0" at 2169,-981 h59.06
  text "2024.05" at 1634.36,-1088.52 h59.06

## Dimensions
-118.12,-1182.29 to -117.65,-4495.41 on Top Overlay
3189.95,-4494.9 to 3189.43,117.87 on Top Overlay
-117.64,-4501.52 to 3190.12,-4495.41 on Top Overlay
